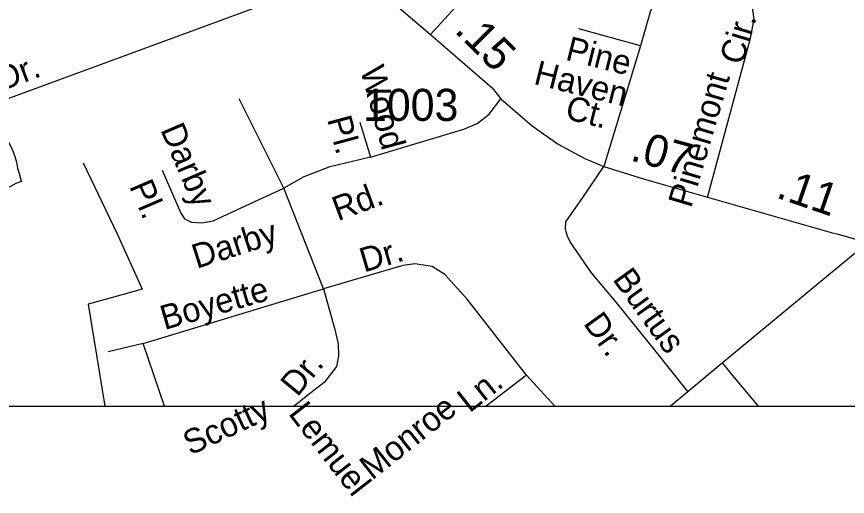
# Model space of a CAD drawing. Extents: x 2315291 to 2336543, y 597177 to 615230.
# Drawn here: x 2318553 to 2321792, y 597177 to 599047 of the extents above; entities that cross this region are included whole.
import ezdxf

# ---------------------------------------------------------------- set-up
doc = ezdxf.new("R2010")
doc.units = 0
for name, color, linetype in [('Exist Boundary Political City Limit New', 7, 'Continuous'), ('Exist Hydrographic Misc Water Feature', 7, 'Continuous'), ('Exist Road Non-System Type 51', 7, 'Continuous'), ('Exist Road Non-System Type 51 Label', 7, 'Continuous'), ('Exist Road Primary US Attributed', 7, 'Continuous'), ('Exist Road Primary US UnDivided 4 Lane Attributed', 7, 'Continuous'), ('Exist Road Secondary Mileage Hundredths English Label', 7, 'Continuous'), ('Exist Road Secondary Type 51 Attributed', 7, 'Continuous'), ('Exist Road Secondary Type 51 Number Label', 7, 'Continuous'), ('Map Preparation Boundary City Limit Buffer Line', 7, 'Continuous')]:
    doc.layers.add(name, color=color, linetype=linetype)

msp = doc.modelspace()

# ---------------------------------------------------------------- linework, layer by layer
at = {"layer": 'Exist Boundary Political City Limit New'}
msp.add_lwpolyline([(2315744.5, 604723.7), (2315744.5, 597529.5), (2327185.3, 597529.5)], dxfattribs=at)
at = {"layer": 'Exist Hydrographic Misc Water Feature'}
for points in [[(2318467.7, 598592.1), (2318477.8, 598595.9), (2318489.9, 598600.1), (2318497.9, 598602.2), (2318512.4, 598584.2), (2318520.4, 598560.7), (2318536.6, 598530.6), (2318546.9, 598502.7), (2318553.4, 598480.7), (2318557.5, 598457), (2318563.5, 598437), (2318565.7, 598424.9), (2318572.3, 598405.2), (2318550.2, 598396.8), (2318526.4, 598384.6), (2318508.3, 598378.4), (2318498.3, 598394.5), (2318485.8, 598434.1), (2318473.3, 598472), (2318445, 598533.5), (2318436.3, 598551.8), (2318430.2, 598575.5), (2318452.3, 598585.9), (2318467.7, 598592.1)], [(2318813, 598477.7), (2318945.9, 598201.4), (2319042.5, 597984.5), (2318936.9, 597955.4), (2318832.9, 597926), (2318897.4, 597529.5)]]:
    msp.add_lwpolyline(points, dxfattribs=at)
at = {"layer": 'Exist Road Non-System Type 51'}
for p, q in [((2320985, 598933.3), (2320744.9, 598999.5)), ((2320985, 598933.3), (2320841.7, 598463.2)), ((2319595.4, 598379.4), (2319421.1, 598727)), ((2319891.5, 598635.7), (2319933.4, 598499.8)), ((2319749.5, 597985.8), (2319595.4, 598379.4)), ((2319046.6, 597773.4), (2319749.5, 597985.8)), ((2319046.6, 597773.4), (2318910.1, 597741)), ((2319129.6, 597529.5), (2319046.6, 597773.4)), ((2320652, 597529.5), (2320541.2, 597650.3))]:
    msp.add_line(p, q, dxfattribs=at)
for points in [[(2320167.2, 598977.2), (2320347, 599176), (2320452.4, 599301.8), (2320502.5, 599358.6), (2320543, 599389.8), (2320566, 599403.3), (2320598.4, 599420.9)], [(2321245.9, 598342.2), (2321413.5, 598963), (2321428.4, 599037.4), (2321421.6, 599082), (2321400, 599134.8), (2321379.7, 599163.2), (2321314.1, 599198), (2321210.8, 599214.6), (2321139.1, 599197), (2321091.8, 599171.3), (2321060.7, 599141.6), (2321024.2, 599069.9), (2320985, 598933.3)], [(2319933.4, 598499.8), (2320297, 598609.3), (2320348.4, 598631), (2320371.3, 598647.2), (2320395.7, 598667.5), (2320440.3, 598727)], [(2319933.4, 598499.8), (2319769.8, 598460.5), (2319672.5, 598422.7), (2319595.4, 598379.4)], [(2321170.3, 597586.3), (2321037.7, 597753.1), (2320890.4, 597934.4), (2320794.9, 598048.8), (2320711.6, 598169.9), (2320701.3, 598191.7), (2320693.1, 598217.8), (2320694.6, 598247.6), (2320714.4, 598277.9), (2320757.8, 598338.4), (2320841.7, 598463.2)], [(2319121.4, 598448.6), (2319193.1, 598281.5), (2319207.4, 598259.7), (2319235.6, 598246), (2319275.1, 598244.1), (2319319.7, 598250.9), (2319448.1, 598311.8), (2319595.4, 598379.4)], [(2320541.2, 597650.3), (2320310.2, 597945.6), (2320222.6, 598042.6), (2320172.6, 598073.7), (2320138.8, 598079.1), (2320105, 598083.2), (2320059.1, 598077.8), (2319749.5, 597985.8)], [(2319749.5, 597985.8), (2319793.8, 597828.3), (2319806.3, 597771.4), (2319807.7, 597725.4), (2319800.9, 597683.5), (2319752.2, 597621.3), (2319700.9, 597580.7), (2319642.8, 597536), (2319634.6, 597529.5)], [(2321303.6, 597697.8), (2321355.4, 597634.2), (2321443.8, 597529.5)], [(2320541.2, 597650.3), (2320383.1, 597529.5)]]:
    msp.add_lwpolyline(points, dxfattribs=at)
at = {"layer": 'Exist Road Non-System Type 51 Label'}
msp.add_lwpolyline([(2319875.9, 599227.8), (2318529.3, 598730.4), (2318439.4, 598697), (2318076.9, 598562.3), (2317685.5, 598416.9), (2317200.8, 598235.4), (2317018.9, 598167.2), (2317008.3, 598164.2), (2316938.9, 598144.3), (2316832.2, 598110), (2316707.5, 598081.8), (2316590.7, 598067.7), (2316575.1, 598066.8), (2316290.6, 598049.6), (2316055, 598033.5), (2315908, 598023.4), (2315833.5, 598018.4), (2315744.5, 597990.8)], dxfattribs=at)
at = {"layer": 'Exist Road Primary US Attributed'}
msp.add_line((2321000.7, 598414.1), (2321728.6, 598206.6), dxfattribs=at)
msp.add_lwpolyline([(2321756.1, 598071.9), (2321872.6, 598168.2)], dxfattribs=at)
msp.add_arc((2324469.9, 607823.5), 10000, 254.08936, 256.23807, dxfattribs=at)
at = {"layer": 'Exist Road Primary US UnDivided 4 Lane Attributed'}
msp.add_lwpolyline([(2321100.8, 597529.5), (2321170.3, 597586.3), (2321303.6, 597697.8), (2321756.1, 598071.9)], dxfattribs=at)
at = {"layer": 'Exist Road Secondary Type 51 Attributed'}
msp.add_lwpolyline([(2319875.9, 599227.8), (2320167.2, 598977.2), (2320407.2, 598770.3), (2320440.3, 598727), (2320562.9, 598622), (2320664.7, 598550.5), (2320712, 598524.8), (2320768.7, 598495), (2320841.7, 598463.2), (2321000.7, 598414.1)], dxfattribs=at)
at = {"layer": 'Map Preparation Boundary City Limit Buffer Line'}
msp.add_lwpolyline([(2315744.5, 604723.7), (2315744.5, 597529.5), (2327185.3, 597529.5)], dxfattribs=at)

# ---------------------------------------------------------------- texts
at = {"layer": 'Exist Road Non-System Type 51 Label'}
for s, rotation, p in [('Cir.', 73.5058, (2321382.7, 598855.1)), ('Pine', 345.9309, (2320688.9, 598879.8)), ('Dr.', 20.7896, (2318496.2, 598756.3)), ('Wood', 285.2055, (2319892.1, 598841.4)), ('Haven', 345.9309, (2320565.1, 598785.8)), ('Pinemont', 73.5058, (2321182.4, 598298.2)), ('Ct.', 345.9309, (2320687.2, 598650.2)), ('Pl.', 285.2055, (2319763.2, 598647.4)), ('Darby', 293.2233, (2319112.8, 598607)), ('Pl.', 293.2233, (2318991.1, 598386.5)), ('Rd.', 20.3483, (2319805.6, 598249.6)), ('Darby', 17.7696, (2319255.2, 598064.3)), ('Dr.', 16.4266, (2319907.2, 598049.8)), ('Burtus', 305.8546, (2320873.8, 598023.6)), ('Boyette', 15.9976, (2319129.6, 597825.5)), ('Dr.', 305.8546, (2320759.7, 597851.2)), ('Dr.', 50.3547, (2319647.5, 597562.2)), ('Ln.', 38.4365, (2320319.4, 597500.4)), ('Monroe', 38.4365, (2319939, 597238.4)), ('Scotty', 25.1518, (2319230.6, 597335.9)), ('Lemuel', 307.8269, (2319610.1, 597499.7))]:
    msp.add_text(s, height=95, rotation=rotation, dxfattribs=at).set_placement(p)
at = {"layer": 'Exist Road Secondary Mileage Hundredths English Label'}
for s, rotation, p in [('.15', 315.0297, (2320256.6, 598989.5)), ('.07', 344.6721, (2320941.6, 598488.1)), ('.11', 341.0302, (2321509.5, 598343.3))]:
    msp.add_text(s, height=125, rotation=rotation, dxfattribs=at).set_placement(p)
at = {"layer": 'Exist Road Secondary Type 51 Number Label'}
msp.add_text('1003', height=125, dxfattribs=at).set_placement((2319903.6, 598641))

doc.saveas('drawing.dxf')
